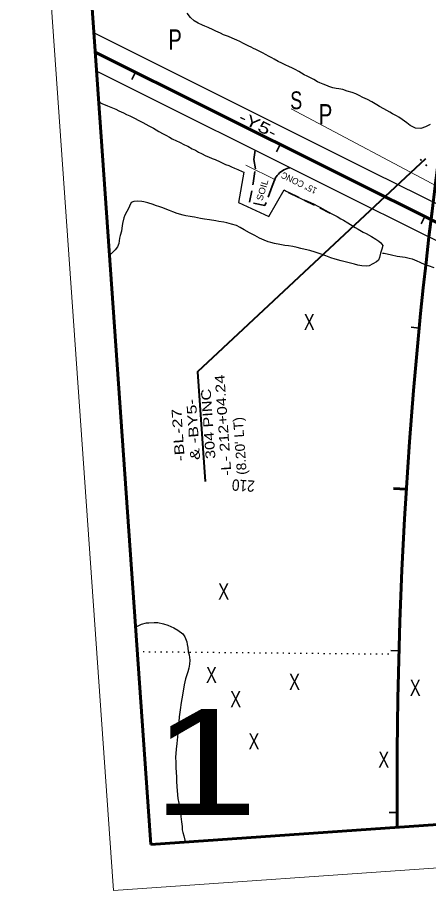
# Model space of a CAD drawing. Extents: x 2399800 to 2400616, y 567347 to 568869.
# Drawn here: x 2399917 to 2400171, y 567968 to 568508 of the extents above; entities that cross this region are included whole.
import ezdxf
from ezdxf.enums import TextEntityAlignment as Align

# ---------------------------------------------------------------- set-up
doc = ezdxf.new("R2010")
doc.units = 0
doc.header["$LTSCALE"] = 2.4
for name, pattern in [('DOTTED', [1.5, 0.3, -1.2]), ('LONG_DASHED', [7.5, 6, -1.5]), ('MEDIUM_DASHED', [4.5, 3, -1.5])]:
    doc.linetypes.add(name, pattern=pattern)
for name, color, linetype, lineweight in [('1', 7, 'Continuous', 40), ('11', 7, 'Continuous', 25), ('18', 7, 'Continuous', 13), ('21', 7, 'Continuous', 40), ('26', 7, 'LONG_DASHED', 35), ('3', 7, 'MEDIUM_DASHED', 35), ('38', 7, 'Continuous', 13), ('4', 7, 'Continuous', 35), ('6', 7, 'Continuous', 13), ('61', 7, 'Continuous', 40), ('62', 7, 'Continuous', 60), ('63', 7, 'Continuous', 35)]:
    doc.layers.add(name, color=color, linetype=linetype, lineweight=lineweight)
for name, color, linetype in [('14', 7, 'Continuous'), ('2', 7, 'Continuous'), ('23', 7, 'Continuous'), ('51', 7, 'Continuous'), ('9', 7, 'Continuous')]:
    doc.layers.add(name, color=color, linetype=linetype)

msp = doc.modelspace()

# ---------------------------------------------------------------- linework, layer by layer
at = {"layer": '1'}
msp.add_line((2399965.144, 568485.991), (2400484.477, 568226.976), dxfattribs=at)
at = {"layer": '11', "linetype": 'DOTTED'}
msp.add_line((2399991.059, 568115.389), (2400148.956, 568113.896), dxfattribs=at)
at = {"layer": '11'}
for points in [[(2400172.174, 568441.366), (2400169.319, 568439.913), (2400166.298, 568438.938), (2400163.125, 568439.125), (2400159.839, 568440.775), (2400157.76, 568442.341), (2400156.381, 568443.436), (2400154.832, 568444.4), (2400152.818, 568445.882), (2400151.25, 568446.696), (2400148.898, 568447.919), (2400147.2, 568448.902), (2400145.426, 568449.896), (2400143.588, 568450.975), (2400140.9, 568452.545), (2400139.277, 568453.519), (2400136.086, 568455.308), (2400133.379, 568456.728), (2400130.512, 568458.094), (2400128.225, 568459.231), (2400126.152, 568460.264), (2400123.975, 568461.083), (2400120.751, 568462.038), (2400118.199, 568462.905), (2400115.609, 568463.473), (2400114.112, 568463.669), (2400112.026, 568464.019), (2400109.55, 568464.877), (2400108.606, 568465.228), (2400105.935, 568466.34), (2400103.992, 568467.204), (2400102.544, 568467.774), (2400100.202, 568469.071), (2400098.643, 568469.961), (2400096.076, 568471.287), (2400094.358, 568472.121), (2400090.887, 568474.098), (2400088.684, 568475.301), (2400086.686, 568476.324), (2400085.183, 568477.054), (2400082.456, 568478.325), (2400080.384, 568479.358), (2400078.227, 568480.326), (2400075.744, 568481.717), (2400074.326, 568482.512), (2400072.253, 568483.545), (2400070.844, 568484.415), (2400068.407, 568485.572), (2400066.839, 568486.387), (2400064.422, 568487.693), (2400062.919, 568488.423), (2400061.49, 568489.143), (2400060.052, 568489.789), (2400058.044, 568490.737), (2400056.691, 568491.447), (2400054.404, 568492.584), (2400052.611, 568493.429), (2400049.669, 568494.804), (2400047.577, 568495.687), (2400044.457, 568496.858), (2400042.449, 568497.806), (2400039.648, 568499.086), (2400038.005, 568499.911), (2400034.839, 568501.316), (2400032.822, 568502.189), (2400031.458, 568502.824), (2400028.657, 568504.106), (2400026.334, 568505.552), (2400023.995, 568507.457), (2400021.923, 568510.241)], [(2399967.292, 568455.269), (2399969.251, 568454.423), (2399972.69, 568452.923), (2399974.828, 568452.122), (2399977.821, 568450.753), (2399979.636, 568449.838), (2399982.486, 568448.564), (2399984.529, 568447.62), (2399986.563, 568446.601), (2399989.775, 568445.129), (2399991.647, 568444.052), (2399994.631, 568442.608), (2399996.351, 568441.549), (2399998.224, 568440.472), (2400001.047, 568438.971), (2400002.777, 568437.988), (2400004.507, 568437.006), (2400007.035, 568435.617), (2400008.698, 568434.72), (2400011.017, 568433.511), (2400012.747, 568432.529), (2400015.369, 568431.283), (2400017.26, 568430.358), (2400020.235, 568428.838), (2400022.278, 568427.894), (2400025.101, 568426.392), (2400027.058, 568425.382), (2400029.007, 568424.296), (2400030.746, 568423.39), (2400033.435, 568422.058), (2400035.117, 568421.313), (2400037.454, 568420.256), (2400039.155, 568419.663), (2400042.291, 568418.2), (2400043.089, 568417.794), (2400045.721, 568416.624), (2400047.64, 568415.927), (2400049.331, 568415.258), (2400051.231, 568414.409), (2400053.208, 568413.55)], [(2400053.208, 568413.55), (2400055.982, 568412.285), (2400057.056, 568411.824)], [(2400057.04, 568411.831), (2400053.691, 568393.196), (2400072.371, 568384.475), (2400081.905, 568400.875)], [(2400081.905, 568400.875), (2400083.1, 568400.181), (2400084.336, 568399.567), (2400086.521, 568398.529), (2400088.564, 568397.585), (2400091.387, 568396.084), (2400093.496, 568395.055), (2400095.254, 568394.3), (2400098.123, 568393.178), (2400100.024, 568392.329), (2400102.704, 568390.922), (2400104.376, 568390.101), (2400107.18, 568388.448), (2400109.414, 568387.172), (2400110.859, 568386.379), (2400113.101, 568385.179), (2400114.698, 568384.367), (2400117.008, 568383.083), (2400118.51, 568382.128), (2400121.162, 568380.493), (2400122.882, 568379.435), (2400125.753, 568377.696), (2400127.702, 568376.61), (2400130.649, 568374.862), (2400132.53, 568373.861), (2400135.847, 568371.99), (2400138.509, 568370.432), (2400140.439, 568369.193), (2400141.618, 568368.124), (2400142.8, 568366.438), (2400142.236, 568364.348), (2400141.464, 568361.822), (2400140.75, 568359.134), (2400140.223, 568357.348), (2400138.945, 568356.348), (2400136.803, 568355.223), (2400134.499, 568354.04), (2400132.678, 568353.646), (2400129.935, 568353.905), (2400127.38, 568354.449), (2400125.434, 568354.918), (2400122.813, 568355.547), (2400121.246, 568355.97), (2400118.7, 568356.59), (2400117.133, 568357.012), (2400113.477, 568357.999), (2400110.808, 568358.865), (2400107.644, 568360.1), (2400104.253, 568361.363), (2400101.146, 568362.437), (2400097.87, 568363.377), (2400094.86, 568363.977), (2400092.172, 568364.691), (2400089.997, 568365.188), (2400087.224, 568365.836), (2400084.575, 568366.237), (2400082.23, 568366.601), (2400079.277, 568367.039), (2400075.964, 568367.676), (2400073.58, 568368.353), (2400072.022, 568368.851), (2400069.523, 568369.851), (2400066.749, 568371.115), (2400063.774, 568372.635), (2400060.439, 568374.354), (2400057.273, 568376.206), (2400054.763, 568377.746), (2400052.36, 568378.888), (2400049.387, 568379.792), (2400046.547, 568380.524), (2400044.581, 568380.842), (2400041.572, 568381.441), (2400039.673, 568381.674), (2400035.827, 568382.375), (2400032.723, 568382.832), (2400030.235, 568383.291), (2400028.345, 568383.598), (2400026.389, 568383.992), (2400025.032, 568384.235), (2400023.816, 568384.384), (2400021.186, 568384.937), (2400019.382, 568385.312), (2400015.735, 568386.375), (2400013.066, 568387.241), (2400010.937, 568388.118), (2400009.322, 568388.778), (2400006.823, 568389.777), (2400004.971, 568390.389)], [(2400004.971, 568390.389), (2400002.454, 568391.237), (2400000.981, 568391.802), (2399997.647, 568392.904), (2399995.254, 568393.505), (2399993.981, 568393.815), (2399991.447, 568393.894), (2399989.037, 568393.726), (2399987.331, 568393.01), (2399986.226, 568390.909), (2399985.377, 568389.009), (2399984.583, 568387.564), (2399983.375, 568385.245), (2399982.876, 568383.688), (2399981.984, 568380.174), (2399981.545, 568377.221), (2399981.246, 568375.407), (2399980.617, 568372.786), (2399980.185, 568371.143), (2399979.7, 568367.811), (2399978.975, 568365.664), (2399977.509, 568363.762), (2399974.981, 568361.373), (2399973.894, 568360.859)], [(2400142.718, 568361.851), (2400143.629, 568361.739), (2400148.282, 568360.707), (2400151.739, 568359.976), (2400156.752, 568359.363), (2400159.145, 568358.762), (2400160.93, 568358.235), (2400163.875, 568357.104), (2400165.776, 568356.255), (2400168.836, 568354.802), (2400170.907, 568354.086), (2400174.459, 568352.88)], [(2399990.01, 568130.397), (2399992.152, 568131.432), (2399993.772, 568132.247), (2399996.744, 568133.066), (2399998.283, 568133.215), (2400001.505, 568133.328), (2400003.876, 568133.375), (2400007.33, 568132.615), (2400009.911, 568131.624), (2400013.617, 568130.157), (2400016.137, 568128.667), (2400019.221, 568126.262), (2400020.536, 568124.581), (2400021.667, 568121.403), (2400021.983, 568119.844), (2400022.258, 568117.952), (2400022.598, 568115.208), (2400023.227, 568113.442), (2400023.672, 568110.179), (2400023.346, 568107.516), (2400022.895, 568105.206), (2400022.277, 568102.917), (2400020.896, 568098.526), (2400020.115, 568094.905), (2400018.988, 568088.456), (2400018.272, 568083.983)], [(2400018.272, 568083.983), (2400017.536, 568079.343), (2400017.007, 568075.017), (2400016.566, 568068.652), (2400016.077, 568064.658), (2400015.49, 568058.48), (2400015.229, 568054.965), (2400014.785, 568049.952), (2400014.938, 568047.062), (2400014.99, 568043.34), (2400015.204, 568040.949), (2400015.296, 568037.559), (2400015.364, 568035.355), (2400015.602, 568031.779), (2400015.817, 568029.388), (2400016.01, 568026.831), (2400016.245, 568024.606), (2400016.731, 568021.676), (2400017.047, 568020.117), (2400017.574, 568017.519), (2400017.723, 568015.98), (2400018.084, 568013.402), (2400018.363, 568010.159), (2400018.849, 568007.228), (2400018.937, 568005.191), (2400019.233, 568003.465), (2400019.821, 568001.367), (2400020.514, 567998.748), (2400020.945, 567997.537)]]:
    msp.add_lwpolyline(points, dxfattribs=at)
at = {"layer": '18'}
msp.add_line((2400086.216, 568451.054), (2400266.761, 568354.939), dxfattribs=at)
at = {"layer": '21'}
msp.add_lwpolyline([(2400169.181, 568420.085), (2400028.381, 568288.307), (2400033.118, 568220.573)], dxfattribs=at)
at = {"layer": '26', "linetype": 'MEDIUM_DASHED'}
msp.add_line((2400084.549, 568399.391), (2400113.482, 568384.96), dxfattribs=at)
at = {"layer": '3', "linetype": 'Continuous', "lineweight": 60}
msp.add_line((2400157.377, 568215.779), (2400149.393, 568216.279), dxfattribs=at)
at = {"layer": '3', "linetype": 'Continuous', "lineweight": 25}
for points in [[(2400483.629, 568239.104), (2400470.246, 568245.798), (2400419.343, 568271.108), (2400362.072, 568299.673), (2400308.009, 568326.642), (2400253.449, 568353.932), (2400194.927, 568382.951), (2400136.831, 568411.76), (2400076.265, 568441.964), (2400023.623, 568468.434), (2399965.535, 568497.344), (2399964.308, 568497.949)], [(2400485.284, 568215.439), (2400462, 568226.988), (2400409.841, 568252.853), (2400354.423, 568280.585), (2400297.876, 568308.829), (2400245.542, 568334.846), (2400186.098, 568364.488), (2400128.133, 568393.345), (2400067.555, 568423.559), (2400013.737, 568450.439), (2399965.96, 568474.329)]]:
    msp.add_lwpolyline(points, dxfattribs=at)
at = {"layer": '3'}
msp.add_lwpolyline([(2400085.469, 568414.624), (2400084.721, 568414.441), (2400083.695, 568414.108), (2400082.697, 568413.699), (2400081.731, 568413.218), (2400080.803, 568412.667), (2400079.919, 568412.049), (2400079.083, 568411.367), (2400078.299, 568410.625), (2400077.572, 568409.827), (2400076.906, 568408.977), (2400076.305, 568408.081), (2400076.277, 568408.036), (2400074.543, 568403.209), (2400069.985, 568391.17), (2400060.545, 568393.314), (2400062.672, 568405.089), (2400064.095, 568413.974), (2400063.174, 568419.797), (2400063.911, 568425.379)], dxfattribs=at)
at = {"layer": '38'}
msp.add_line((2399965.144, 568485.991), (2400484.477, 568226.976), dxfattribs=at)
at = {"layer": '4'}
for p, q in [((2399989.928, 568473.63), (2399987.696, 568469.156)), ((2400079.415, 568428.999), (2400077.183, 568424.525)), ((2400168.903, 568384.367), (2400166.671, 568379.893)), ((2400165.349, 568315.456), (2400160.372, 568315.94)), ((2400152.846, 568115.887), (2400147.848, 568116.027)), ((2400151.763, 568015.897), (2400146.763, 568015.865))]:
    msp.add_line(p, q, dxfattribs=at)
at = {"layer": '6'}
msp.add_line((2400076.558, 568407.093), (2400058.178, 568416.176), dxfattribs=at)
at = {"layer": '62'}
msp.add_line((2399965.144, 568485.991), (2400484.477, 568226.976), dxfattribs=at)
msp.add_arc((2403051.703, 568034.46), 2900, 170.48821, 180.54867, dxfattribs=at)
at = {"layer": '63', "lineweight": 13}
for p in [(2399917.038, 568815.546), (2400524.992, 568005.982)]:
    msp.add_line(p, (2399976.331, 567967.616), dxfattribs=at)
at = {"layer": '63', "lineweight": 60}
for q in [(2399943.373, 568797.338), (2400498.188, 568030.909)]:
    msp.add_line((2399999.405, 567996.031), q, dxfattribs=at)

# ---------------------------------------------------------------- texts
at = {"layer": '11', "width": 0.75}
for p in [(2400097.398, 568314.166), (2400044.501, 568147.538), (2400036.94, 568095.932), (2400088.295, 568091.654), (2400162.92, 568087.922), (2400051.928, 568080.952), (2400063.214, 568054.869), (2400143.467, 568043.587)]:
    msp.add_text('X', height=10, dxfattribs=at).set_placement(p, align=Align.CENTER)
at = {"layer": '14', "width": 0.75}
for p in [(2400014.464, 568487.635), (2400107.481, 568441.428)]:
    msp.add_text('P', height=12.5, dxfattribs=at).set_placement(p, align=Align.CENTER)
at = {"layer": '2'}
msp.add_text(':', height=7.5, rotation=45, dxfattribs=at).set_placement((2400170.158, 568415.758), align=Align.CENTER)
at = {"layer": '21'}
for s, width, p in [('-L- 212+04.24 ', 1.25, (2400049.292, 568224.23)), ('304 PINC', 1.25, (2400039.446, 568234.709)), ('& -BY5-', 1.35, (2400029.969, 568234.046)), ('-BL-27  ', 1.35, (2400020.492, 568233.383)), ("(8.20' LT)", 1.05, (2400058.769, 568224.892))]:
    msp.add_text(s, height=6, rotation=94, dxfattribs=dict(at, width=width)).set_placement(p)
at = {"layer": '23', "width": 1.1}
msp.add_text('SOIL', height=4, rotation=73.424, dxfattribs=at).set_placement((2400070.311, 568400.225), align=Align.CENTER)
at = {"layer": '26', "width": 0.95}
msp.add_text('15" CONC', height=4, rotation=153.938, dxfattribs=at).set_placement((2400091.975, 568406.991), align=Align.CENTER)
at = {"layer": '51', "width": 1.35}
msp.add_text('1', height=65.62, dxfattribs=at).set_placement((2400033.039, 568014.257), align=Align.CENTER)
at = {"layer": '61'}
for s, rotation, width, p in [('-Y5-', 333.493, 1.4, (2400064.176, 568438.058)), ('210', 176.415, 0.9, (2400056.873, 568221.537))]:
    msp.add_text(s, height=7, rotation=rotation, dxfattribs=dict(at, width=width)).set_placement(p, align=Align.CENTER)
at = {"layer": '9', "width": 0.75}
msp.add_text('S', height=11, dxfattribs=at).set_placement((2400089.359, 568450.815), align=Align.CENTER)

doc.saveas('drawing.dxf')
